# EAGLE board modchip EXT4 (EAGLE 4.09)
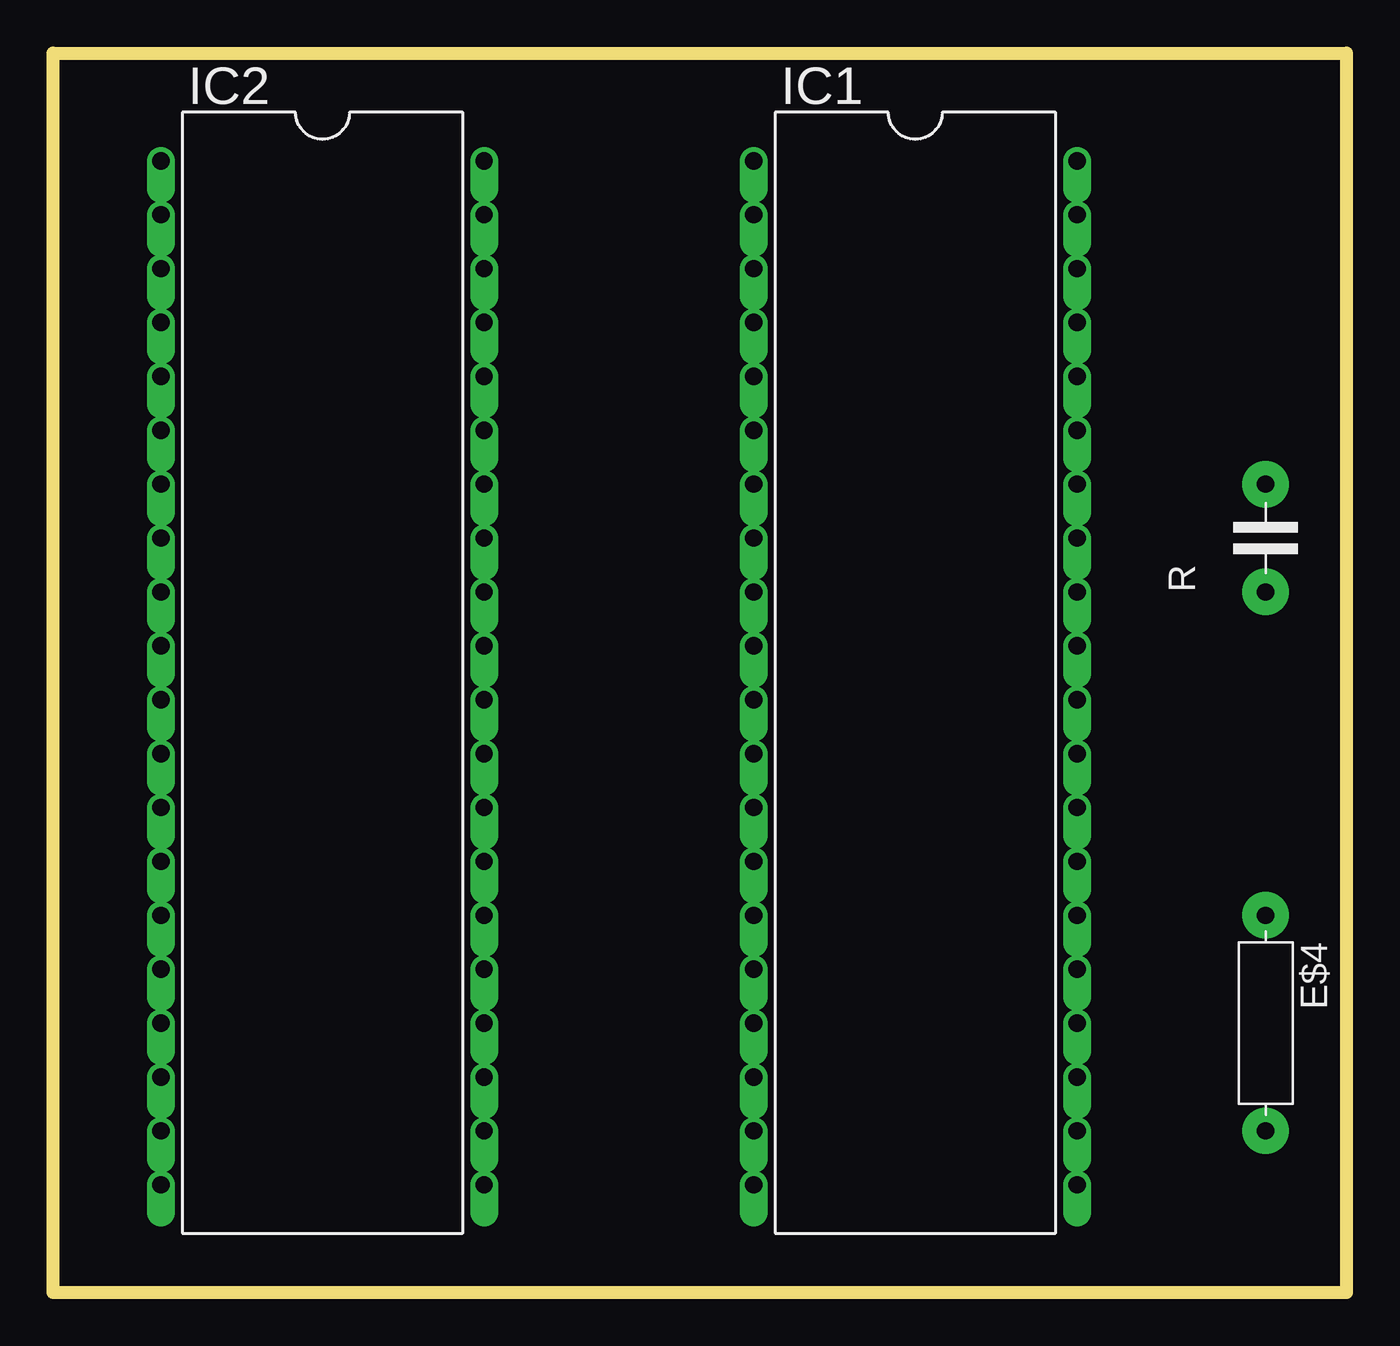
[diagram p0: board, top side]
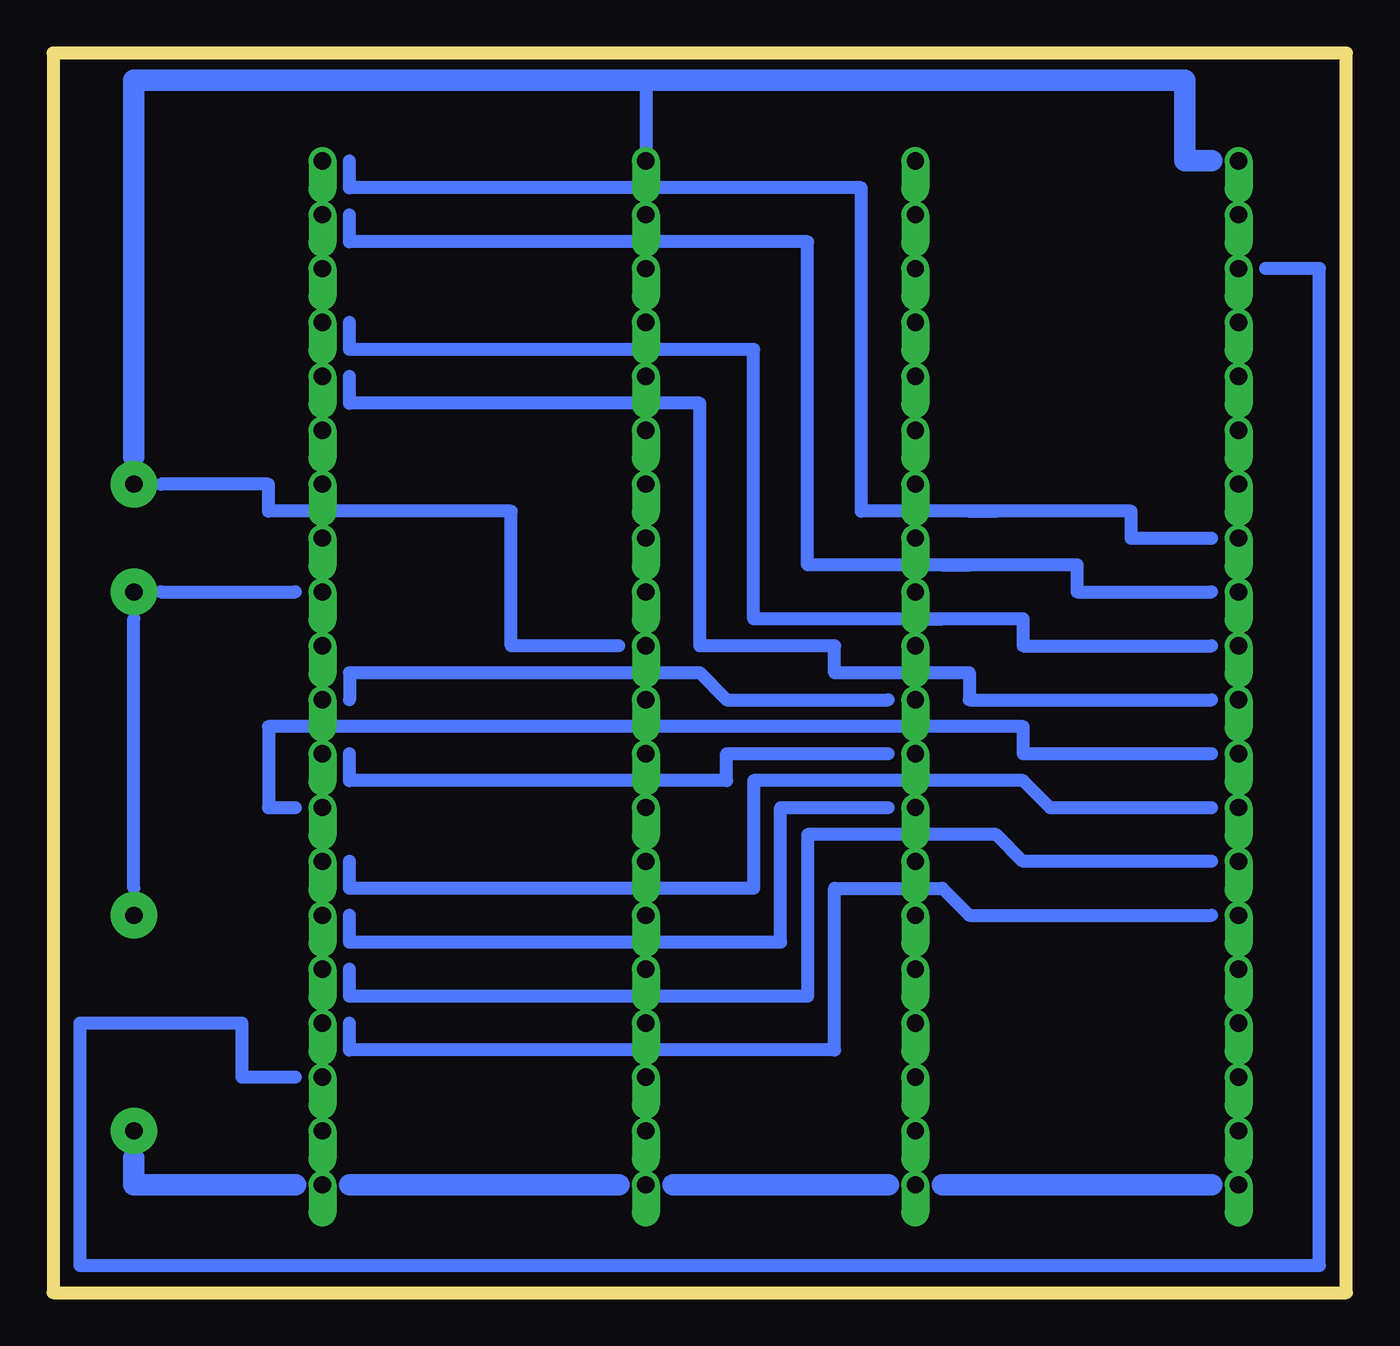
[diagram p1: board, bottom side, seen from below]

Size 60.96 x 58.42 mm. Coordinates in mm from the lower left corner, seen from the top.
Outline: 60.96,58.42 60.96,0 0,0 0,58.42 60.96,58.42
Copper layers used: Bottom

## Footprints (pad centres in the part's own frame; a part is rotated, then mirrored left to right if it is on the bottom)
L-10 = drill 0.813 pad 1.6 octagon: 1 -5.08,0; 2 5.08,0
DIL40 = drill 0.813 offset: 1 -24.13,-7.62; 2 -21.59,-7.62; 3 -19.05,-7.62; 4 -16.51,-7.62; 5 -13.97,-7.62; 6 -11.43,-7.62; 7 -8.89,-7.62; 8 -6.35,-7.62; 9 -3.81,-7.62; 10 -1.27,-7.62; 11 1.27,-7.62; 12 3.81,-7.62; 13 6.35,-7.62; 14 8.89,-7.62; 15 11.43,-7.62; 16 13.97,-7.62; 17 16.51,-7.62; 18 19.05,-7.62; 19 21.59,-7.62; 20 24.13,-7.62; 21 24.13,7.62; 22 21.59,7.62; 23 19.05,7.62; 24 16.51,7.62; 25 13.97,7.62; 26 11.43,7.62; 27 8.89,7.62; 28 6.35,7.62; 29 3.81,7.62; 30 1.27,7.62; 31 -1.27,7.62; 32 -3.81,7.62; 33 -6.35,7.62; 34 -8.89,7.62; 35 -11.43,7.62; 36 -13.97,7.62; 37 -16.51,7.62; 38 -19.05,7.62; 39 -21.59,7.62; 40 -24.13,7.62
C-5 = drill 0.813 pad 1.6 octagon: 1 -2.54,0; 2 2.54,0

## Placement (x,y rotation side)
E$4  8k2  [L-10]  57.15,12.7 270 top
IC1  [DIL40]  40.64,29.21 270 top
IC2  [DIL40]  12.7,29.21 270 top
R  10uF  [C-5]  57.15,35.56 90 top

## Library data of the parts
E$4 R = discrete
IC1 IC2 = dil

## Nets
S$1: R.1
S$14: IC1.1
S$20: IC1.21 IC1.22
S$54: R.2

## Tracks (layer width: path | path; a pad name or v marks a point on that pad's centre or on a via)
S$1  (via drill 0.61 pad 2.18)
  other vias: 57.15,33.02
S$3
  Bottom 1.016: 49.53,5.08 57.15,5.08 57.15,6.35
S$8
  Bottom 0.61: 46.99,27.94 46.99,29.21 30.48,29.21 29.21,27.94 21.59,27.94
S$10
  Bottom 0.61: 49.53,10.16 52.07,10.16 52.07,12.7 59.69,12.7 59.69,1.27 1.27,1.27 1.27,48.26 3.81,48.26
S$14
  Bottom 0.61: 33.02,57.15 IC1.1
  Bottom 1.016: 6.35,53.34 7.62,53.34 7.62,57.15 33.02,57.15 57.15,57.15 57.15,39.37
S$15
  Bottom 0.61: 46.99,25.4 46.99,24.13 29.21,24.13 29.21,25.4 21.59,25.4
S$20
  Bottom 0.61: 48.26,6.35 IC1.21 IC1.22
S$31
  Bottom 0.61: 49.53,22.86 50.8,22.86 50.8,26.67 15.24,26.67 15.24,25.4 6.35,25.4
S$32
  Bottom 0.61: 46.99,43.18 46.99,41.91 30.48,41.91 30.48,30.48 24.13,30.48 24.13,29.21 17.78,29.21 17.78,27.94 6.35,27.94
S$33
  Bottom 0.61: 46.99,20.32 46.99,19.05 27.94,19.05 27.94,24.13 15.24,24.13 13.97,22.86 6.35,22.86
S$34
  Bottom 0.61: 46.99,17.78 46.99,16.51 26.67,16.51 26.67,22.86 21.59,22.86
S$35
  Bottom 0.61: 46.99,45.72 46.99,44.45 27.94,44.45 27.94,31.75 20.32,31.75 | 20.32,31.75 19.05,31.75 | 20.32,31.75 15.24,31.75 15.24,30.48 6.35,30.48
S$36
  Bottom 0.61: 46.99,53.34 46.99,52.07 22.86,52.07 22.86,36.83 17.78,36.83 | 17.78,36.83 16.51,36.83 | 17.78,36.83 10.16,36.83 10.16,35.56 6.35,35.56
S$37
  Bottom 0.61: 46.99,15.24 46.99,13.97 25.4,13.97 25.4,21.59 16.51,21.59 15.24,20.32 6.35,20.32
S$38
  Bottom 0.61: 46.99,50.8 46.99,49.53 25.4,49.53 25.4,34.29 19.05,34.29 | 19.05,34.29 17.78,34.29 | 19.05,34.29 12.7,34.29 12.7,33.02 6.35,33.02
S$39
  Bottom 0.61: 46.99,12.7 46.99,11.43 24.13,11.43 24.13,19.05 19.05,19.05 17.78,17.78 6.35,17.78
S$41
  Bottom 1.016: 46.99,5.08 34.29,5.08
S$42
  Bottom 1.016: 31.75,5.08 21.59,5.08
S$43
  Bottom 1.016: 19.05,5.08 6.35,5.08
S$48  (via drill 0.61 pad 2.18)
  other vias: 57.15,17.78
S$49  (via drill 0.61 pad 2.18)
  other vias: 57.15,7.62
S$51
  Bottom 0.61: 55.88,33.02 49.53,33.02
S$52
  Bottom 0.61: 57.15,19.05 57.15,31.75
S$53
  Bottom 0.61: 34.29,30.48 39.37,30.48 39.37,36.83 50.8,36.83 50.8,38.1 55.88,38.1
S$54  (via drill 0.61 pad 2.18)
  other vias: 57.15,38.1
